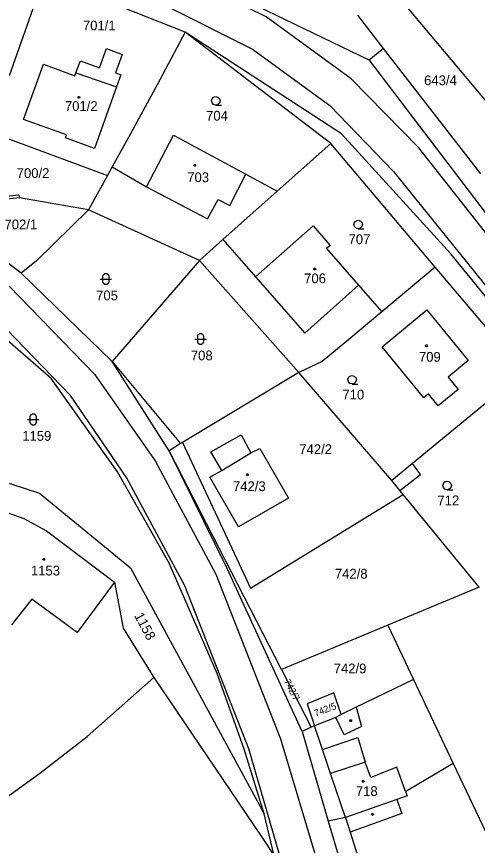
# Model space of a CAD drawing. Extents: x -621797 to -620972, y -1175539 to -1174697.
# Drawn here: x -621393.6 to -621313.4, y -1175130.5 to -1174986.3 of the extents above; entities that cross this region are included whole.
import ezdxf

# ---------------------------------------------------------------- set-up
doc = ezdxf.new("R2010")
doc.units = 0
for name, color, linetype in [('Rozvod plynu EON', 7, 'Continuous'), ('SDEL EON', 7, 'Continuous'), ('SDEL EON - popis', 7, 'Continuous'), ('Silnoproud EON', 7, 'Continuous'), ('Silnoproud EON - popis', 7, 'Continuous')]:
    doc.layers.add(name, color=color, linetype=linetype)

msp = doc.modelspace()

# ---------------------------------------------------------------- linework, layer by layer
at = {"layer": 'Rozvod plynu EON'}
for points in [[(-621382.65, -1175000.18), (-621382.56, -1175000.33), (-621382.65, -1175000.48), (-621382.83, -1175000.48), (-621382.92, -1175000.33), (-621382.83, -1175000.18)], [(-621362.5, -1175012.02), (-621362.41, -1175012.17), (-621362.5, -1175012.32), (-621362.68, -1175012.32), (-621362.77, -1175012.17), (-621362.68, -1175012.02)], [(-621341.64, -1175030.06), (-621341.55, -1175030.21), (-621341.64, -1175030.36), (-621341.82, -1175030.36), (-621341.91, -1175030.21), (-621341.82, -1175030.06)], [(-621322.2, -1175043.44), (-621322.11, -1175043.59), (-621322.2, -1175043.74), (-621322.38, -1175043.74), (-621322.47, -1175043.59), (-621322.38, -1175043.44)], [(-621353.34, -1175065.85), (-621353.25, -1175066), (-621353.34, -1175066.15), (-621353.52, -1175066.15), (-621353.61, -1175066), (-621353.52, -1175065.85)], [(-621388.77, -1175080.59), (-621388.68, -1175080.74), (-621388.77, -1175080.89), (-621388.95, -1175080.89), (-621389.04, -1175080.74), (-621388.95, -1175080.59)], [(-621335.38, -1175108.68), (-621335.29, -1175108.83), (-621335.38, -1175108.98), (-621335.56, -1175108.98), (-621335.65, -1175108.83), (-621335.56, -1175108.68)], [(-621333.19, -1175119.25), (-621333.1, -1175119.4), (-621333.19, -1175119.55), (-621333.37, -1175119.55), (-621333.46, -1175119.4), (-621333.37, -1175119.25)], [(-621331.58, -1175124.97), (-621331.49, -1175125.12), (-621331.58, -1175125.27), (-621331.76, -1175125.27), (-621331.85, -1175125.12), (-621331.76, -1175124.97)]]:
    msp.add_lwpolyline(points, close=True, dxfattribs=at)
at = {"layer": 'SDEL EON'}
for points in [[(-621358.93, -1175001.69), (-621359.31, -1175001.59), (-621359.58, -1175001.32), (-621359.68, -1175000.95), (-621359.58, -1175000.58), (-621359.31, -1175000.31), (-621358.94, -1175000.21), (-621358.57, -1175000.31), (-621358.3, -1175000.58), (-621358.2, -1175000.96), (-621358.3, -1175001.34), (-621358.57, -1175001.61), (-621358.95, -1175001.71), (-621357.95, -1175001.71)], [(-621334.15, -1175023.19), (-621334.53, -1175023.09), (-621334.8, -1175022.82), (-621334.9, -1175022.45), (-621334.8, -1175022.08), (-621334.53, -1175021.81), (-621334.16, -1175021.71), (-621333.79, -1175021.81), (-621333.52, -1175022.08), (-621333.42, -1175022.46), (-621333.52, -1175022.84), (-621333.79, -1175023.11), (-621334.17, -1175023.21), (-621333.17, -1175023.21)], [(-621379.06, -1175031.96), (-621377.79, -1175031.96), (-621377.06, -1175031.96)], [(-621362.58, -1175042.41), (-621361.31, -1175042.41), (-621360.58, -1175042.41)], [(-621335.21, -1175050.22), (-621335.59, -1175050.12), (-621335.86, -1175049.85), (-621335.96, -1175049.48), (-621335.86, -1175049.11), (-621335.59, -1175048.84), (-621335.22, -1175048.74), (-621334.85, -1175048.84), (-621334.58, -1175049.11), (-621334.48, -1175049.49), (-621334.58, -1175049.87), (-621334.85, -1175050.14), (-621335.23, -1175050.24), (-621334.23, -1175050.24)], [(-621391.7, -1175056.41), (-621390.43, -1175056.41), (-621389.7, -1175056.41)], [(-621318.68, -1175068.64), (-621319.06, -1175068.54), (-621319.33, -1175068.27), (-621319.43, -1175067.9), (-621319.33, -1175067.53), (-621319.06, -1175067.26), (-621318.69, -1175067.16), (-621318.32, -1175067.26), (-621318.05, -1175067.53), (-621317.95, -1175067.91), (-621318.05, -1175068.29), (-621318.32, -1175068.56), (-621318.7, -1175068.66), (-621317.7, -1175068.66)]]:
    msp.add_lwpolyline(points, dxfattribs=at)
for points in [[(-621378.56, -1175031.46), (-621378.46, -1175031.17), (-621378.21, -1175030.99), (-621377.9, -1175030.99), (-621377.65, -1175031.17), (-621377.55, -1175031.46), (-621377.55, -1175032.46), (-621377.65, -1175032.75), (-621377.9, -1175032.93), (-621378.21, -1175032.93), (-621378.46, -1175032.75), (-621378.56, -1175032.46)], [(-621362.08, -1175041.91), (-621361.98, -1175041.62), (-621361.73, -1175041.44), (-621361.42, -1175041.44), (-621361.17, -1175041.62), (-621361.07, -1175041.91), (-621361.07, -1175042.91), (-621361.17, -1175043.2), (-621361.42, -1175043.38), (-621361.73, -1175043.38), (-621361.98, -1175043.2), (-621362.08, -1175042.91)], [(-621391.2, -1175055.91), (-621391.1, -1175055.62), (-621390.85, -1175055.44), (-621390.54, -1175055.44), (-621390.29, -1175055.62), (-621390.19, -1175055.91), (-621390.19, -1175056.91), (-621390.29, -1175057.2), (-621390.54, -1175057.38), (-621390.85, -1175057.38), (-621391.1, -1175057.2), (-621391.2, -1175056.91)]]:
    msp.add_lwpolyline(points, close=True, dxfattribs=at)
at = {"layer": 'SDEL EON - popis'}
for p, q in [((-621350.15, -1174986.32), (-621364.76, -1174979.08)), ((-621368.03, -1174984.17), (-621352.56, -1174991.96)), ((-621335.41, -1174997.12), (-621350.15, -1174986.32)), ((-621352.56, -1174991.96), (-621339.11, -1175001.74)), ((-621383.26, -1174996.06), (-621376.19, -1174998.49)), ((-621323.62, -1175009.12), (-621335.41, -1174997.12)), ((-621339.11, -1175001.74), (-621328.01, -1175013.22)), ((-621282.85, -1175060.98), (-621323.62, -1175009.12)), ((-621328.01, -1175013.22), (-621287.02, -1175064.24)), ((-621356.52, -1175019.14), (-621353.7, -1175013.73)), ((-621370.99, -1175015.9), (-621360.4, -1175021.51)), ((-621397.16, -1175017.74), (-621393.22, -1175017.3)), ((-621393.22, -1175017.3), (-621393.11, -1175017.81)), ((-621360.4, -1175021.51), (-621358.54, -1175018.11)), ((-621358.54, -1175018.11), (-621356.52, -1175019.14)), ((-621352.01, -1175031.59), (-621343.43, -1175041.38)), ((-621394.86, -1175033.18), (-621380.01, -1175048.54)), ((-621343.43, -1175041.38), (-621334.08, -1175033.04)), ((-621384.23, -1175052.21), (-621398.61, -1175037.31)), ((-621376.96, -1175046.31), (-621365.06, -1175060.59)), ((-621380.01, -1175048.54), (-621369.49, -1175063.63)), ((-621374.45, -1175066.49), (-621384.23, -1175052.21)), ((-621357.86, -1175065.27), (-621352.83, -1175062.22)), ((-621369.49, -1175063.63), (-621358.94, -1175083.35)), ((-621323.34, -1175066.01), (-621324.69, -1175064.07)), ((-621364.3, -1175085.37), (-621374.45, -1175066.49)), ((-621326.9, -1175068.78), (-621323.34, -1175066.01)), ((-621358.94, -1175083.35), (-621347.7, -1175112.01)), ((-621353.17, -1175113.73), (-621364.3, -1175085.37)), ((-621334.51, -1175106.45), (-621333.56, -1175109.87)), ((-621336.62, -1175111.31), (-621338.08, -1175108.26)), ((-621340.39, -1175113.82), (-621341.75, -1175109.71)), ((-621333.56, -1175109.87), (-621336.62, -1175111.31)), ((-621347.7, -1175112.01), (-621340.8, -1175134.9)), ((-621340.39, -1175113.82), (-621334.24, -1175111.78)), ((-621334.24, -1175111.78), (-621332.97, -1175116.04)), ((-621346.63, -1175136.41), (-621353.17, -1175113.73)), ((-621339, -1175118.01), (-621340.39, -1175113.82)), ((-621332.97, -1175116.04), (-621339, -1175118.01)), ((-621331.99, -1175118.72), (-621332.97, -1175116.04)), ((-621327.42, -1175116.9), (-621331.99, -1175118.72)), ((-621325.93, -1175121.13), (-621327.42, -1175116.9)), ((-621336.39, -1175125.7), (-621339, -1175118.01)), ((-621327.46, -1175122.56), (-621326.59, -1175124.96)), ((-621336.39, -1175125.7), (-621335.58, -1175128.26)), ((-621326.59, -1175124.96), (-621335.58, -1175128.26)), ((-621335.58, -1175128.26), (-621334.24, -1175132.49))]:
    msp.add_line(p, q, dxfattribs=at)
at = {"layer": 'Silnoproud EON'}
for p, q in [((-621388.75, -1174979.17), (-621394.87, -1174996.57)), ((-621364.26, -1174989.02), (-621388.75, -1174979.17)), ((-621332.26, -1174993.86), (-621360.13, -1174980.38)), ((-621305.54, -1175008.66), (-621327.66, -1174982.17)), ((-621329.73, -1174991.82), (-621334.24, -1174986.03)), ((-621364.26, -1174989.02), (-621369.14, -1174998.17)), ((-621337.06, -1175006.7), (-621364.26, -1174989.02)), ((-621338.95, -1175008.36), (-621364.26, -1174989.02)), ((-621379.17, -1174995.2), (-621377.95, -1174991.86)), ((-621377.95, -1174991.86), (-621375.23, -1174992.86)), ((-621375.23, -1174992.86), (-621376.38, -1174996.08)), ((-621329.73, -1174991.82), (-621332.26, -1174993.86)), ((-621312.83, -1175013.67), (-621329.73, -1174991.82)), ((-621392.39, -1175004.19), (-621388.92, -1174994.58)), ((-621388.92, -1174994.58), (-621383.45, -1174996.57)), ((-621383.26, -1174996.06), (-621382.5, -1174993.98)), ((-621382.5, -1174993.98), (-621379.17, -1174995.2)), ((-621332.26, -1174993.86), (-621281.81, -1175060.17)), ((-621383.45, -1174996.57), (-621383.26, -1174996.06)), ((-621376.38, -1174996.08), (-621375.44, -1174996.42)), ((-621375.44, -1174996.42), (-621376.19, -1174998.49)), ((-621376.19, -1174998.49), (-621380.06, -1175009.23)), ((-621369.14, -1174998.17), (-621374.08, -1175007.2)), ((-621384.91, -1175006.89), (-621392.39, -1175004.19)), ((-621398.31, -1175006.37), (-621377.79, -1175013.96)), ((-621385.1, -1175007.41), (-621384.91, -1175006.89)), ((-621380.06, -1175009.23), (-621385.1, -1175007.41)), ((-621374.08, -1175007.2), (-621376.96, -1175012.46)), ((-621370.99, -1175015.9), (-621366.3, -1175006.92)), ((-621366.3, -1175006.92), (-621353.7, -1175013.73)), ((-621318.03, -1175027.56), (-621337.06, -1175006.7)), ((-621338.95, -1175008.36), (-621348.26, -1175016.67)), ((-621320.75, -1175029.91), (-621338.95, -1175008.36)), ((-621377.37, -1175013.19), (-621377.79, -1175013.96)), ((-621376.96, -1175012.46), (-621377.37, -1175013.19)), ((-621376.96, -1175012.46), (-621370.99, -1175015.9)), ((-621377.79, -1175013.96), (-621381.06, -1175019.93)), ((-621353.7, -1175013.73), (-621348.26, -1175016.67)), ((-621348.26, -1175016.67), (-621357.7, -1175025.09)), ((-621393.11, -1175017.81), (-621397.73, -1175018.35)), ((-621381.06, -1175019.93), (-621393.11, -1175017.81)), ((-621381.06, -1175019.93), (-621390.1, -1175028.8)), ((-621361.76, -1175028.72), (-621381.06, -1175019.93)), ((-621392.81, -1175030.95), (-621403.95, -1175022.42)), ((-621352.01, -1175031.59), (-621342, -1175022.73)), ((-621342, -1175022.73), (-621339.05, -1175026.11)), ((-621357.7, -1175025.09), (-621361.76, -1175028.72)), ((-621357.7, -1175025.09), (-621352.01, -1175031.59)), ((-621339.05, -1175026.11), (-621339.65, -1175026.63)), ((-621339.65, -1175026.63), (-621334.08, -1175033.04)), ((-621287.81, -1175064.86), (-621318.03, -1175027.56)), ((-621390.1, -1175028.8), (-621392.81, -1175030.95)), ((-621361.76, -1175028.72), (-621376.96, -1175046.31)), ((-621344.47, -1175048.24), (-621361.76, -1175028.72)), ((-621320.75, -1175029.91), (-621330.03, -1175037.69)), ((-621305.4, -1175048.11), (-621320.75, -1175029.91)), ((-621387.58, -1175049.25), (-621407.96, -1175031.58)), ((-621376.96, -1175046.31), (-621392.81, -1175030.95)), ((-621334.08, -1175033.04), (-621330.03, -1175037.69)), ((-621330.03, -1175037.69), (-621335.79, -1175042.51)), ((-621330.01, -1175043.76), (-621322.21, -1175037.35)), ((-621322.21, -1175037.35), (-621315.03, -1175046.12)), ((-621335.79, -1175042.51), (-621340.43, -1175046.29)), ((-621322.77, -1175052.64), (-621330.01, -1175043.76)), ((-621367.02, -1175061.87), (-621376.96, -1175046.31)), ((-621340.43, -1175046.29), (-621344.47, -1175048.24)), ((-621315.03, -1175046.12), (-621318.48, -1175049.04)), ((-621376.02, -1175065.52), (-621387.58, -1175049.25)), ((-621344.47, -1175048.24), (-621364.75, -1175060.41)), ((-621328.32, -1175067.04), (-621344.47, -1175048.24)), ((-621305.4, -1175048.11), (-621324.69, -1175064.07)), ((-621318.48, -1175049.04), (-621316.76, -1175051.21)), ((-621321.94, -1175051.95), (-621322.77, -1175052.64)), ((-621320.22, -1175054.05), (-621321.94, -1175051.95)), ((-621316.76, -1175051.21), (-621320.22, -1175054.05)), ((-621359.82, -1175062.01), (-621354.53, -1175059.06)), ((-621354.53, -1175059.06), (-621352.83, -1175062.22)), ((-621365.06, -1175060.59), (-621367.02, -1175061.87)), ((-621364.75, -1175060.41), (-621365.06, -1175060.59)), ((-621364.75, -1175060.41), (-621352.91, -1175085.78)), ((-621357.01, -1175082.25), (-621367.02, -1175061.87)), ((-621347.49, -1175099.94), (-621367.02, -1175061.87)), ((-621357.86, -1175065.27), (-621359.82, -1175062.01)), ((-621352.83, -1175062.22), (-621351.28, -1175061.43)), ((-621351.28, -1175061.43), (-621346.27, -1175070.12)), ((-621404.88, -1175064.31), (-621389.62, -1175069.25)), ((-621359.99, -1175066.45), (-621357.86, -1175065.27)), ((-621324.69, -1175064.07), (-621328.32, -1175067.04)), ((-621367.05, -1175081.42), (-621376.02, -1175065.52)), ((-621355.01, -1175075.1), (-621359.99, -1175066.45)), ((-621326.9, -1175068.78), (-621328.32, -1175067.04)), ((-621389.62, -1175069.25), (-621373.78, -1175082.22)), ((-621352.91, -1175085.78), (-621326.36, -1175069.44)), ((-621326.36, -1175069.44), (-621326.9, -1175068.78)), ((-621313.11, -1175085.57), (-621326.36, -1175069.44)), ((-621401.72, -1175070.37), (-621392.32, -1175073.64)), ((-621346.27, -1175070.12), (-621355.01, -1175075.1)), ((-621392.32, -1175073.64), (-621388.4, -1175075.81)), ((-621388.4, -1175075.81), (-621376.56, -1175084.7)), ((-621373.78, -1175082.22), (-621350.54, -1175125.06)), ((-621358.7, -1175100.59), (-621367.05, -1175081.42)), ((-621343.93, -1175110.69), (-621357.01, -1175082.25)), ((-621376.56, -1175084.7), (-621383.07, -1175093.49)), ((-621376.56, -1175084.7), (-621375.05, -1175092.73)), ((-621313.11, -1175085.57), (-621328.99, -1175092.21)), ((-621391.42, -1175088.25), (-621394.5, -1175092.17)), ((-621390.96, -1175087.67), (-621391.42, -1175088.25)), ((-621383.07, -1175093.49), (-621390.96, -1175087.67)), ((-621375.05, -1175092.73), (-621369.74, -1175101.33)), ((-621328.99, -1175092.21), (-621347.49, -1175099.94)), ((-621328.99, -1175092.21), (-621324.52, -1175101.66)), ((-621347.49, -1175099.94), (-621342.34, -1175109.98)), ((-621381.34, -1175111.6), (-621369.74, -1175101.33)), ((-621369.74, -1175101.33), (-621351.04, -1175128.93)), ((-621353.99, -1175113.81), (-621358.7, -1175100.59)), ((-621324.52, -1175101.66), (-621334.51, -1175106.45)), ((-621324.52, -1175101.66), (-621317.61, -1175116.28)), ((-621338.41, -1175103.99), (-621343.02, -1175105.92)), ((-621337.14, -1175107.78), (-621338.41, -1175103.99)), ((-621343.02, -1175105.92), (-621341.75, -1175109.71)), ((-621334.51, -1175106.45), (-621337.14, -1175107.78)), ((-621338.08, -1175108.26), (-621341.75, -1175109.71)), ((-621337.14, -1175107.78), (-621338.08, -1175108.26)), ((-621342.34, -1175109.98), (-621343.93, -1175110.69)), ((-621341.75, -1175109.71), (-621342.34, -1175109.98)), ((-621343.93, -1175110.69), (-621339.39, -1175126.33)), ((-621389.63, -1175118.02), (-621381.34, -1175111.6)), ((-621350.54, -1175125.06), (-621353.99, -1175113.81)), ((-621317.61, -1175116.28), (-621325.46, -1175120.92)), ((-621317.61, -1175116.28), (-621310.86, -1175130.56)), ((-621446.08, -1175158.75), (-621389.63, -1175118.02)), ((-621325.46, -1175120.92), (-621325.93, -1175121.13)), ((-621325.93, -1175121.13), (-621325.65, -1175121.93)), ((-621327.46, -1175122.56), (-621336.39, -1175125.7)), ((-621325.65, -1175121.93), (-621327.46, -1175122.56)), ((-621348.77, -1175132.34), (-621350.54, -1175125.06)), ((-621336.39, -1175125.7), (-621339.39, -1175126.33)), ((-621339.39, -1175126.33), (-621337.37, -1175133.15)), ((-621351.04, -1175128.93), (-621348.77, -1175132.34))]:
    msp.add_line(p, q, dxfattribs=at)

# ---------------------------------------------------------------- texts
at = {"layer": 'Silnoproud EON - popis'}
for s, p in [('701/1', (-621382.053, -1174988.68)), ('643/4', (-621322.693, -1174998.22)), ('701/2', (-621385.183, -1175002.7)), ('704', (-621360.623, -1175004.39)), ('700/2', (-621393.57, -1175014.37)), ('703', (-621363.903, -1175015.1)), ('702/1', (-621395.693, -1175023.31)), ('707', (-621335.843, -1175025.89)), ('706', (-621343.563, -1175032.69)), ('705', (-621379.753, -1175035.66)), ('708', (-621363.273, -1175046.11)), ('709', (-621323.593, -1175046.36)), ('710', (-621336.903, -1175052.92)), ('1159', (-621392.607, -1175060.11)), ('742/2', (-621344.403, -1175062.43)), ('742/3', (-621355.943, -1175068.87)), ('712', (-621320.373, -1175071.34)), ('1153', (-621391.097, -1175083.56)), ('742/8', (-621338.213, -1175084.1)), ('742/9', (-621338.423, -1175100.59)), ('718', (-621334.563, -1175121.93))]:
    msp.add_text(s, height=1.7, dxfattribs=at).set_placement(p)
for s, height, rotation, p in [('1158', 1.7, 297.88076, (-621373.166, -1175090.537)), ('742/7', 1.19, 297.19321, (-621347.124, -1175101.968)), ('742/5', 1.19, 20.68378, (-621341.575, -1175108.151))]:
    msp.add_text(s, height=height, rotation=rotation, dxfattribs=at).set_placement(p)

doc.saveas('drawing.dxf')
